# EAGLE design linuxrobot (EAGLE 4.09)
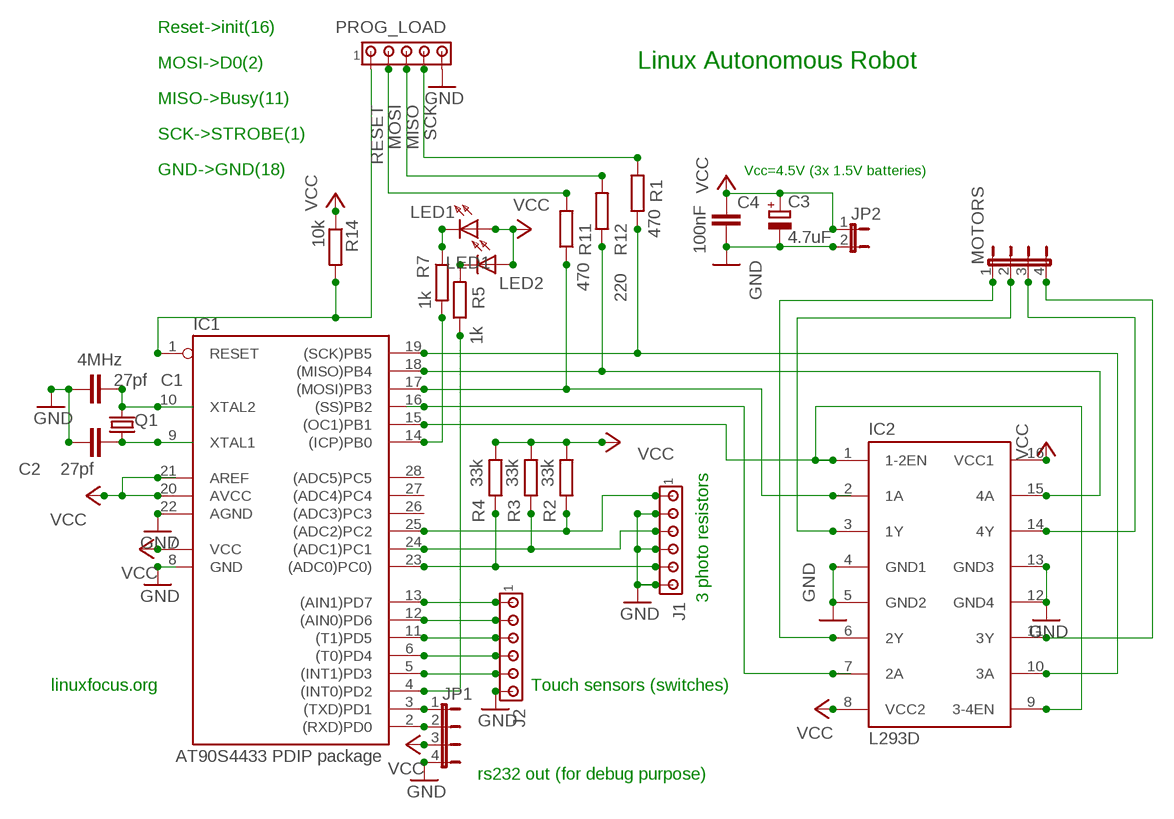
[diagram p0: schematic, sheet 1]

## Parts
C1  27pf  C2.5/2  [C2.5-2]
C2  27pf  C2.5/2  [C2.5-2]
C3  4.7uF  CPOL-EUE2.5-7  [E2,5-7]
C4  100nF  C-EU025-040X050  [C025-040X050]
IC1  AT90S4433 PDIP package  AT90S4433P  [DIL28-3]
IC2  L293D  [DIL16]
J1  MTA06-100  [10X06MTA]
J2  MTA06-100  [10X06MTA]
JP1  JP4E  [JP4]
JP2  JP1E  [JP1]
LED1  LED1  LED3MM  [LED3MM]
LED2  LED3MM  [LED3MM]
MOTORS  JP4E  [JP4]
PROG_LOAD  MTA05-100  [10X05MTA]
Q1  4MHz  HC49U-V  [HC49U-V]
R1  470  R-EU_0204/7  [0204/7]
R2  33k  R-EU_0204/5  [0204/5]
R3  33k  R-EU_0204/7  [0204/7]
R4  33k  R-EU_0204/5  [0204/5]
R5  1k  R-EU_0204/7  [0204/7]
R7  1k  R-EU_0204/7  [0204/7]
R11  470  R-EU_0204/7  [0204/7]
R12  220  R-EU_0204/7  [0204/7]
R14  10k  R-EU_0204/7  [0204/7]

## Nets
D7: IC1.17((MOSI)PB3) IC2.2(1A) R11.1
GND: C1.1 C2.1 C3.- C4.2 IC1.8(GND) IC1.22(AGND) IC2.4(GND1) IC2.5(GND2) IC2.12(GND4) IC2.13(GND3) J1.1 J1.3 J1.5 J2.1 JP1.4 JP2.2 PROG_LOAD.5
MISO: PROG_LOAD.3 R12.2
MOSI: PROG_LOAD.2 R11.2
N$1: IC1.15((OC1)PB1) IC2.1(1-2EN) IC2.9(3-4EN)
N$2: C2.2 IC1.9(XTAL1) Q1.1
N$3: IC2.6(2Y) MOTORS.1
N$4: IC1.16((SS)PB2) IC2.7(2A)
N$5: IC1.14((ICP)PB0) R7.2
N$6: IC2.3(1Y) MOTORS.2
N$7: LED1.K(C) R7.1
N$8: IC2.14(4Y) MOTORS.3
N$9: IC2.11(3Y) MOTORS.4
N$10: IC1.23((ADC0)PC0)) J1.2 R4.1
N$11: IC1.24((ADC1)PC1) J1.4 R3.1
N$12: IC1.25((ADC2)PC2) J1.6 R2.1
N$13: IC1.13((AIN1)PD7) J2.6
N$14: IC1.12((AIN0)PD6) J2.5
N$15: IC1.11((T1)PD5) J2.4
N$16: IC1.6((T0)PD4) J2.3
N$17: IC1.3((TXD)PD1) JP1.1
N$18: IC1.2((RXD)PD0) JP1.2
N$19: IC1.5((INT1)PD3) J2.2
N$20: LED2.K(C) R5.2
N$21: IC1.4((INT0)PD2) R5.1
N$36: C1.2 IC1.10(XTAL2) Q1.2
N$41: IC1.18((MISO)PB4) IC2.15(4A) R12.1
R/W: IC1.19((SCK)PB5) IC2.10(3A) R1.1
RESET: IC1.1(RESET) PROG_LOAD.1 R14.2
SCK: PROG_LOAD.4 R1.2
VCC: C3.+ C4.1 IC1.7(VCC) IC1.20(AVCC) IC1.21(AREF) IC2.8(VCC2) IC2.16(VCC1) JP1.3 JP2.1 LED1.A LED2.A R2.2 R3.2 R4.2 R14.1
Unconnected: IC1.26((ADC3)PC3) IC1.27((ADC4)PC4) IC1.28((ADC5)PC5)

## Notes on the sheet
- Reset->init(16)
- MOSI->D0(2) | Linux Autonomous Robot
- MISO->Busy(11)
- SCK->STROBE(1)
- GND->GND(18) | Vcc=4.5V (3x 1.5V batteries)
- 3 photo resistors
- linuxfocus.org | Touch sensors (switches)
- rs232 out (for debug purpose)

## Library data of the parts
C1 C2 = capacitor-wima:C: CAPACITOR
C3 = rcl:CPOL-EU: POLARIZED CAPACITOR, European symbol
C4 = rcl:C-EU: CAPACITOR, European symbol
IC1 = atmel:AT90S4433: MICROCONTROLLER 4 Kbytes FLASH 128 bytes SRAM 256 bytes EEPROM UART 6-channel 10 bit ADC
IC2 = st-microelectronics:L293D: PUSH-PULL 4 CHANNEL DRIVER
J1 J2 = con-amp:MTA06-100: AMP connector
JP1 MOTORS = jumper:JP4E: JUMPER
JP2 = jumper:JP1E: JUMPER
LED1 = led:LED3MM: LED
LED2 = led:LED: LED
PROG_LOAD = con-amp:MTA05-100: AMP connector
Q1 = crystal:HC49U-V: CRYSTAL
R1-R5 R7 R11 R12 R14 = rcl:R-EU_: RESISTOR, European symbol

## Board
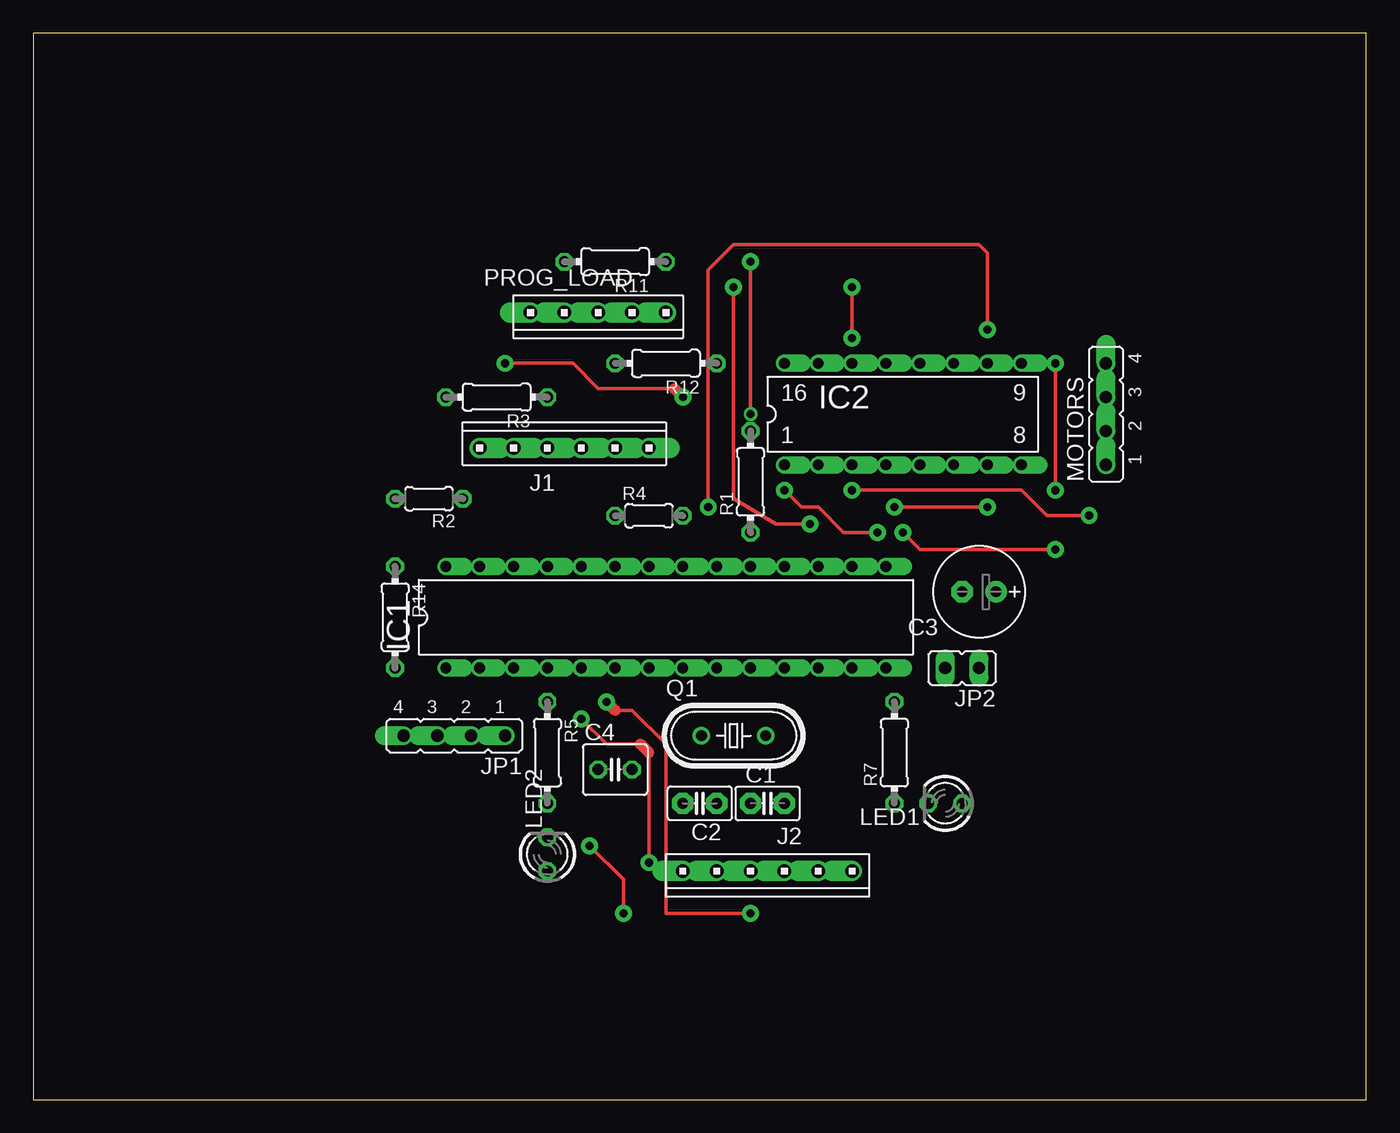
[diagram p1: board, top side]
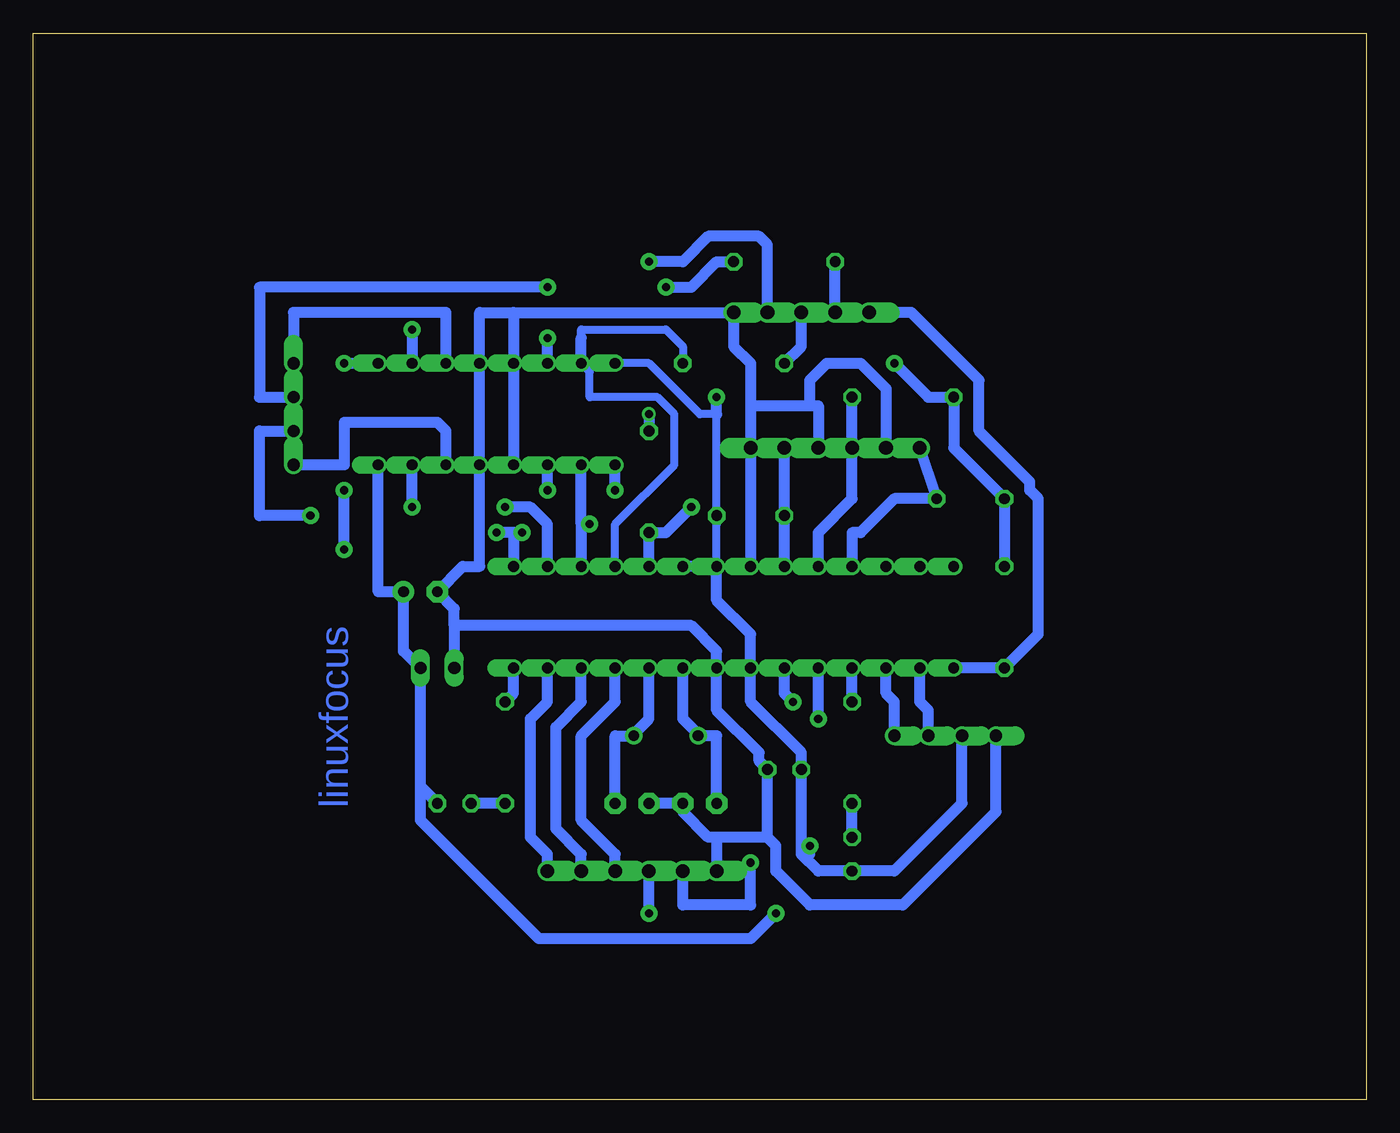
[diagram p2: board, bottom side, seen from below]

Size 100 x 80 mm. Coordinates in mm from the lower left corner, seen from the top.
Outline: 0,0 100,0 100,80 0,80 0,0
Copper layers used: Top, Bottom

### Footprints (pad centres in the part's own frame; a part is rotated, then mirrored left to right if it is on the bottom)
C2.5-2 = drill 0.813 pad 1.6 octagon: 1 -1.27,0; 2 1.27,0
E2,5-7 = drill 0.813 pad 1.6 round: + -1.27,0 | drill 0.813 pad 1.6 octagon: - 1.27,0
C025-040X050 = drill 0.813 octagon: 1 -1.27,0; 2 1.27,0
DIL28-3 = drill 0.813 offset: 1 -16.51,-3.81; 2 -13.97,-3.81; 3 -11.43,-3.81; 4 -8.89,-3.81; 5 -6.35,-3.81; 6 -3.81,-3.81; 7 -1.27,-3.81; 8 1.27,-3.81; 9 3.81,-3.81; 10 6.35,-3.81; 11 8.89,-3.81; 12 11.43,-3.81; 13 13.97,-3.81; 14 16.51,-3.81; 15 16.51,3.81; 16 13.97,3.81; 17 11.43,3.81; 18 8.89,3.81; 19 6.35,3.81; 20 3.81,3.81; 21 1.27,3.81; 22 -1.27,3.81; 23 -3.81,3.81; 24 -6.35,3.81; 25 -8.89,3.81; 26 -11.43,3.81; 27 -13.97,3.81; 28 -16.51,3.81
DIL16 = drill 0.813 offset: 1 -8.89,-3.81; 2 -6.35,-3.81; 3 -3.81,-3.81; 4 -1.27,-3.81; 5 1.27,-3.81; 6 3.81,-3.81; 7 6.35,-3.81; 8 8.89,-3.81; 9 8.89,3.81; 10 6.35,3.81; 11 3.81,3.81; 12 1.27,3.81; 13 -1.27,3.81; 14 -3.81,3.81; 15 -6.35,3.81; 16 -8.89,3.81
10X06MTA = drill 1.016 offset: 1 6.35,0; 2 3.81,0; 3 1.27,0; 4 -1.27,0; 5 -3.81,0; 6 -6.35,0
JP4 = drill 0.914 offset: 1 -3.81,0; 2 -1.27,0; 3 1.27,0; 4 3.81,0
JP1 = drill 0.914 long: 1 0,-1.27; 2 0,1.27
LED3MM = drill 0.813 octagon: A -1.27,0; K 1.27,0
10X05MTA = drill 1.016 offset: 1 5.08,0; 2 2.54,0; 3 0,0; 4 -2.54,0; 5 -5.08,0
HC49U-V = drill 0.813 round: 1 -2.413,0; 2 2.413,0
0204/7 = drill 0.813 octagon: 1 -3.81,0; 2 3.81,0
0204/5 = drill 0.813 octagon: 1 -2.54,0; 2 2.54,0

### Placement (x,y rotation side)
C1  55.08,22.22 0 top
C2  50,22.22 180 top
C3  70.95,38.1 180 top
C4  43.65,24.76 0 top
IC1  47.46,36.19 0 top
IC2  65.24,51.43 0 top
J1  39.84,48.89 0 top
J2  55.08,17.14 180 top
JP1  31.58,27.3 180 top
JP2  69.69,32.38 90 top
LED1  68.41,22.22 180 top
LED2  38.57,18.41 90 top
MOTORS  80.48,51.43 90 top
PROG_LOAD  42.38,59.05 180 top
Q1  52.54,27.3 0 top
R1  53.81,46.35 90 top
R2  29.68,45.08 180 top
R3  34.76,52.7 180 top
R4  46.19,43.81 0 top
R5  38.57,26.03 270 top
R7  64.61,26.03 90 top
R11  43.65,62.86 180 top
R12  47.46,55.24 180 top
R14  27.14,36.19 270 top

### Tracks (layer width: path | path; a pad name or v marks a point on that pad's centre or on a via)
D7  (via drill 0.61 pad 1.27)
  Top 0.254: v52.54,60.96 52.54,45.08 55.71,43.18 v58.25,43.18
  Bottom 0.813: 58.89,43.18 IC1.17 | 58.89,43.18 IC2.2 | R11.1 48.73,62.86 50.63,60.96 v52.54,60.96 | v58.25,43.18 58.89,43.18
GND
  Bottom 0.813: 63.97,59.05 PROG_LOAD.5 47.46,56.51 46.19,55.24 46.19,52.07 | 63.97,59.05 IC2.13 IC2.4 | 63.97,59.05 66.51,59.05 IC2.12 IC2.5 66.51,40 67.78,40 C3.- 68.41,36.83 68.41,35.55 | C1.1 C2.1 51.27,21.58 49.37,19.68 48.73,19.68 | 48.73,19.68 J2.1 | 44.92,19.68 48.73,19.68 | 44.92,19.68 C4.2 45.55,25.39 45.55,26.03 48.73,29.2 IC1.8 48.73,33.65 50.63,35.55 68.41,35.55 | 46.19,52.07 J1.1 IC1.22 | 46.19,52.07 41.74,52.07 | 41.74,52.07 41.11,52.07 J1.3 | 68.41,35.55 JP2.2 | J1.5 36.03,53.34 37.94,55.24 40.48,55.24 41.74,53.97 41.74,52.07 | 44.92,19.68 44.28,19.04 44.28,17.14 41.74,14.6 34.76,14.6 27.77,21.58 JP1.4
MISO
  Bottom 0.813: PROG_LOAD.3 42.38,56.51 R12.2
MOSI
  Bottom 0.813: PROG_LOAD.2 R11.2
N$1  (via drill 0.61 pad 1.27)
  Top 0.254: v76.67,45.72 v76.67,55.24 | v76.67,41.27 66.51,41.27 v65.24,42.54 | v56.35,45.72 57.62,44.45 58.89,44.45 60.8,42.54 v63.34,42.54
  Bottom 0.813: v56.35,45.72 IC2.1 | v63.34,42.54 63.97,42.54 | v76.67,55.24 IC2.9 | v76.67,41.27 v76.67,45.72 | 63.97,42.54 v65.24,42.54 | 63.97,42.54 IC1.15
N$2
  Bottom 0.813: IC1.9 51.27,28.57 50,27.3 Q1.1 48.73,27.3 C2.2
N$3
  Bottom 0.813: IC2.6 69.05,50.16 69.69,50.8 76.67,50.8 76.67,47.62 MOTORS.1
N$4  (via drill 0.61 pad 1.27)
  Top 0.254: v64.61,44.45 v71.59,44.45
  Bottom 0.813: v71.59,44.45 IC2.7 | v64.61,44.45 62.7,44.45 61.43,43.18 IC1.16
N$5
  Bottom 0.813: IC1.14 63.97,30.47 R7.2
N$6  (via drill 0.61 pad 1.27)
  Top 0.254: v61.43,45.72 74.13,45.72 76.03,43.81 v79.21,43.81
  Bottom 0.813: v61.43,45.72 IC2.3 | v79.21,43.81 83.02,43.81 83.02,50.16 MOTORS.2
N$7
  Bottom 0.813: R7.1 LED1.K
N$8  (via drill 0.61 pad 1.27)
  Top 0.254: v61.43,57.15 v61.43,60.96
  Bottom 0.813: IC2.14 v61.43,57.15 | v61.43,60.96 83.02,60.96 83.02,52.7 MOTORS.3
N$9
  Bottom 0.813: IC2.11 69.05,59.05 80.48,59.05 MOTORS.4
N$10
  Bottom 0.813: J1.2 R4.1 IC1.23
N$11
  Bottom 0.813: IC1.24 41.11,42.54 38.57,45.08 J1.4 R3.1
N$12
  Bottom 0.813: J1.6 R2.1 35.39,45.08 37.94,42.54 38.57,42.54 IC1.25
N$13
  Bottom 0.813: IC1.13 61.43,29.84 62.7,28.57 62.7,19.68 61.43,18.41 J2.6
N$14
  Bottom 0.813: IC1.12 58.89,29.84 60.8,27.93 60.8,20.31 58.89,18.41 J2.5
N$15
  Bottom 0.813: IC1.11 56.35,29.84 58.89,27.3 58.89,20.95 56.35,18.41 J2.4
N$16  (via drill 0.61 pad 1.27)
  Top 0.254: v53.81,13.97 47.46,13.97 47.46,26.66 44.92,29.2 43.65,29.2
  Top 0.813: 43.65,29.2 v43.02,29.84
  Bottom 0.813: v53.81,13.97 J2.3 | v43.02,29.84 43.65,30.47 IC1.6
N$17
  Bottom 0.813: IC1.3 36.03,30.47 35.39,29.84 JP1.1
N$18
  Bottom 0.813: IC1.2 33.49,29.84 32.85,29.2 JP1.2
N$19  (via drill 0.61 pad 1.27)
  Top 0.254: v46.19,17.77 46.19,26.03 | 45.55,26.66 43.02,26.66 v41.11,28.57
  Top 0.813: 46.19,26.03 45.55,26.66
  Bottom 0.813: J2.2 51.27,14.6 46.19,14.6 v46.19,17.77 | v41.11,28.57 IC1.5
N$20
  Bottom 0.813: LED2.K R5.2
N$21
  Bottom 0.813: R5.1 IC1.4
N$36
  Bottom 0.813: IC1.10 53.81,28.57 55.08,27.3 Q1.2 56.35,27.3 C1.2
N$41
  Bottom 0.61: 58.89,57.15 58.89,57.78 52.54,57.78 51.27,56.51 R12.1 | IC1.18 56.35,43.18 51.91,47.62 51.91,51.43 53.17,52.7 58.25,52.7 58.25,54.61 IC2.15
  Bottom 0.813: IC2.15 58.89,57.15
R/W  (via drill 0.61 pad 1.27)
  Top 0.254: v50.63,44.45 50.63,62.23 52.54,64.13 70.95,64.13 71.59,63.5 v71.59,57.78
  Bottom 0.813: IC1.19 R1.1 52.54,42.54 v50.63,44.45 | v71.59,57.78 IC2.10
RESET
  Bottom 0.813: IC1.1 R14.2 24.6,34.92 24.6,45.08 25.23,45.72 25.23,46.35 29.04,50.16 29.04,53.97 34.12,59.05 PROG_LOAD.1
SCK  (via drill 0.61, 0.61 pad 1.27)
  Top 0.254: v53.81,62.86 v53.81,51.43
  Bottom 0.813: PROG_LOAD.4 44.92,64.13 45.55,64.77 49.37,64.77 51.27,62.86 v53.81,62.86 | v53.81,51.43 R1.2
VCC  (via drill 0.61 pad 1.27)
  Top 0.254: v35.39,55.24 40.48,55.24 42.38,53.34 48.09,53.34 | v44.28,13.97 44.28,16.5 v41.74,19.04
  Top 0.813: v48.73,52.7 48.09,53.34
  Bottom 0.61: IC2.16 53.81,55.24 50,51.43 48.73,51.43 R4.2 | R4.2 48.73,43.18 | IC1.21 R4.2
  Bottom 0.813: 70.95,23.49 LED1.A | IC2.8 74.13,38.1 C3.+ 72.22,33.65 JP2.1 70.95,23.49 | 42.38,18.41 C4.1 42.38,26.03 46.19,29.84 IC1.7 46.19,34.92 48.73,37.46 IC1.21 IC1.20 | 42.38,18.41 41.11,17.14 LED2.A 35.39,17.14 30.31,22.22 JP1.3 | R14.1 R2.2 30.95,48.89 R3.2 32.85,52.7 v35.39,55.24 | 48.73,51.43 v48.73,52.7 | 70.95,23.49 70.95,20.95 62.06,12.06 46.19,12.06 v44.28,13.97 | 42.38,18.41 v41.74,19.04 | 42.38,18.41 41.74,18.41

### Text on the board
Bottom: linuxfocus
